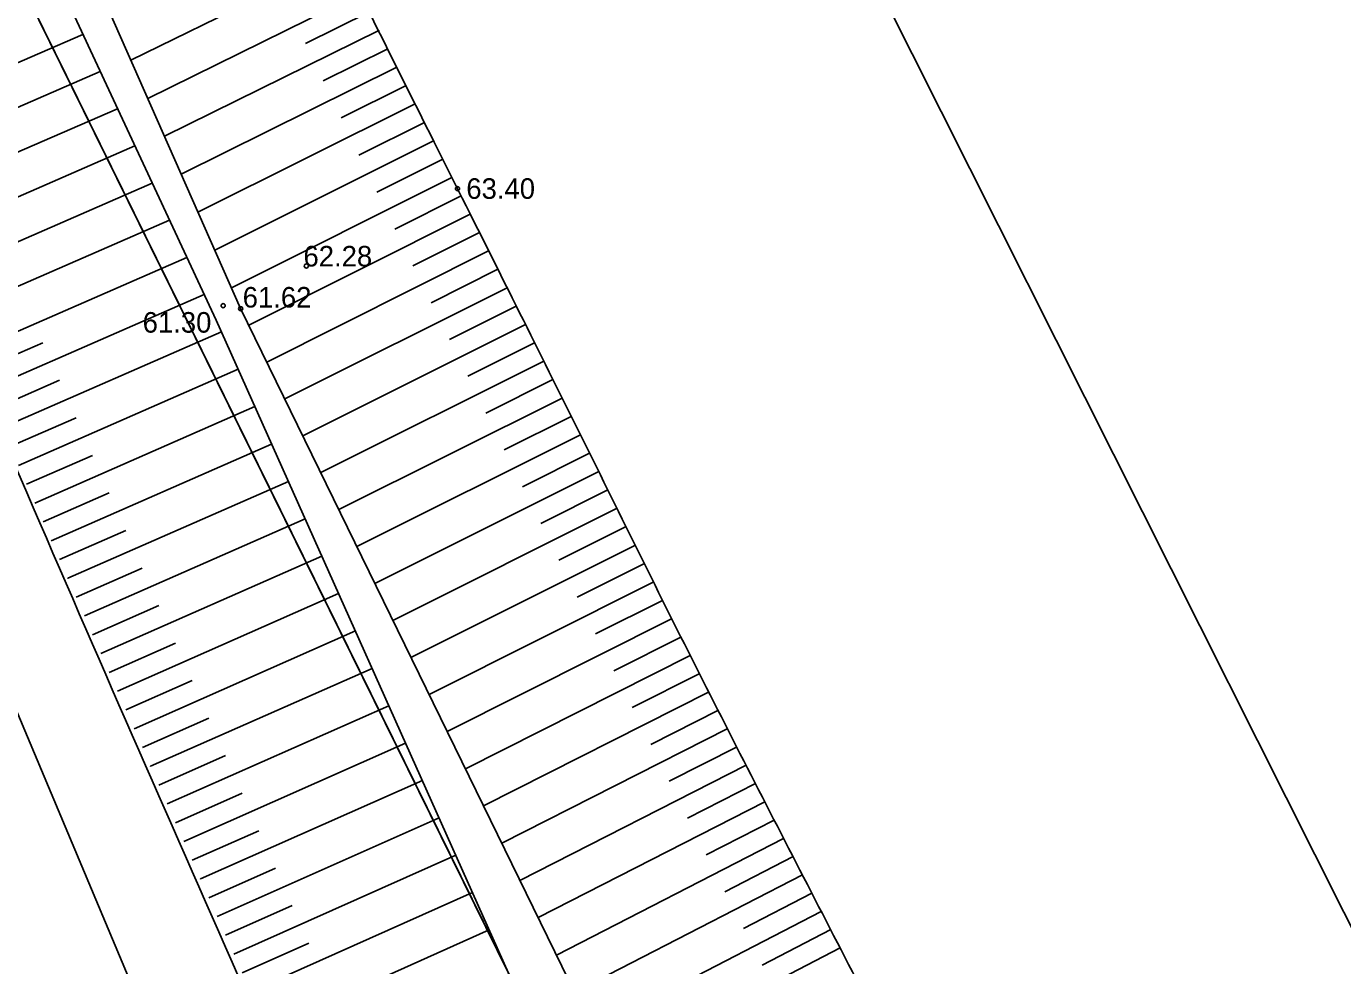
# Model space of a CAD drawing. Extents: x 616607 to 617499, y 408385 to 409695.
# Drawn here: x 617157.39 to 617189.45, y 409191.77 to 409214.63 of the extents above; entities that cross this region are included whole.
import ezdxf

# ---------------------------------------------------------------- set-up
doc = ezdxf.new("R2010")
doc.units = 0
for name, color, linetype in [('HIDG_GRAV_####_####_#', 7, 'Continuous'), ('RAMI_UZMR_####_####_#', 7, 'Continuous'), ('RELJ_AATZ_####_TKST_#', 7, 'Continuous'), ('RELJ_ELEM_####_####_#', 7, 'Continuous'), ('RELJ_NOGA_####_####_#', 7, 'Continuous'), ('ROBZ_IERR_####_####_#', 7, 'Continuous'), ('ROBZ_UZMR_####_####_#', 7, 'Continuous')]:
    doc.layers.add(name, color=color, linetype=linetype)

# ---------------------------------------------------------------- blocks, each defined once
blk = doc.blocks.new('PKT')
at = {"layer": 'RELJ_ELEM_####_####_#'}
blk.add_circle((0, 0), 0.05, dxfattribs=at)

msp = doc.modelspace()

# ---------------------------------------------------------------- linework, layer by layer
at = {"layer": 'HIDG_GRAV_####_####_#'}
for points in [[(617196.049, 409072.553), (617193.886, 409072.979), (617195.921, 409087.874), (617195.921, 409087.874), (617199.518, 409112.516), (617194.569, 409134.842), (617162.019, 409207.474), (617151.93, 409229.107), (617149.428, 409241.28), (617152.359, 409253.938), (617188.564, 409303.055), (617197.968, 409312.659), (617223.456, 409346.169), (617232.567, 409363.51), (617247.671, 409422.509), (617276.576, 409461.456), (617285.007, 409472.526), (617327.765, 409527.3)], [(617198.671, 409072.074), (617200.929, 409072.435), (617202.532, 409075.622), (617201.237, 409087.874), (617202.422, 409112.516), (617197.415, 409136.544), (617162.613, 409207.758), (617153.021, 409229.447), (617150.525, 409241.262), (617153.298, 409253.658), (617189.431, 409302.264), (617198.754, 409312.12), (617224.478, 409345.652), (617234.105, 409363.027), (617250.009, 409421.44), (617285.914, 409471.848), (617328.6, 409526.531)]]:
    msp.add_lwpolyline(points, dxfattribs=at)
at = {"layer": 'RAMI_UZMR_####_####_#'}
msp.add_lwpolyline([(617101.571, 408748.246), (617213.472, 409074.039), (617215.883, 409140.56), (617165.121, 409241.478), (617252.137, 409353.424), (617269.572, 409425.099), (617332.631, 409510.312), (617439.945, 409622.037), (617425.373, 409635.959), (617242.079, 409440.82), (617216.614, 409355.716), (617136.613, 409246.751), (617191.828, 409115.62), (617145.545, 408952.8)], dxfattribs=at)
at = {"layer": 'RELJ_NOGA_####_####_#'}
for p, q in [((617165.091, 409216.326), (617159.938, 409213.805)), ((617165.532, 409215.428), (617160.349, 409212.875)), ((617165.753, 409214.98), (617164.193, 409214.211)), ((617153.607, 409212.193), (617158.773, 409214.434)), ((617165.974, 409214.531), (617160.757, 409211.955)), ((617165.974, 409214.531), (617165.975, 409214.532)), ((617166.196, 409214.083), (617164.626, 409213.306)), ((617166.196, 409214.083), (617166.196, 409214.083)), ((617154.005, 409211.275), (617159.196, 409213.527)), ((617166.418, 409213.635), (617161.166, 409211.029)), ((617166.418, 409213.635), (617166.419, 409213.636)), ((617166.64, 409213.187), (617165.059, 409212.402)), ((617166.64, 409213.187), (617166.641, 409213.187)), ((617166.863, 409212.74), (617161.574, 409210.107)), ((617166.863, 409212.74), (617166.864, 409212.74)), ((617154.403, 409210.358), (617159.618, 409212.623)), ((617167.086, 409212.292), (617165.494, 409211.497)), ((617167.086, 409212.292), (617167.086, 409212.292)), ((617167.309, 409211.845), (617161.981, 409209.185)), ((617167.309, 409211.845), (617167.31, 409211.845)), ((617154.802, 409209.441), (617160.039, 409211.72)), ((617167.533, 409211.397), (617165.929, 409210.594)), ((617167.533, 409211.397), (617167.533, 409211.398)), ((617155.201, 409208.524), (617160.462, 409210.813)), ((617167.757, 409210.95), (617162.389, 409208.263)), ((617167.757, 409210.95), (617167.758, 409210.951)), ((617167.981, 409210.503), (617166.364, 409209.693)), ((617167.981, 409210.503), (617167.981, 409210.503)), ((617155.6, 409207.607), (617160.883, 409209.91)), ((617168.205, 409210.056), (617162.81, 409207.354)), ((617168.205, 409210.056), (617168.206, 409210.057)), ((617168.429, 409209.609), (617166.809, 409208.798)), ((617168.429, 409209.609), (617168.429, 409209.609)), ((617155.999, 409206.69), (617161.306, 409209.004)), ((617168.652, 409209.162), (617163.247, 409206.459)), ((617168.652, 409209.162), (617168.653, 409209.162)), ((617168.876, 409208.715), (617167.253, 409207.903)), ((617168.876, 409208.715), (617168.876, 409208.715)), ((617169.099, 409208.267), (617163.685, 409205.564)), ((617169.099, 409208.267), (617169.1, 409208.268)), ((617156.399, 409205.774), (617161.726, 409208.101)), ((617169.323, 409207.82), (617167.697, 409207.009)), ((617169.323, 409207.82), (617169.323, 409207.82)), ((617169.546, 409207.373), (617164.124, 409204.666)), ((617169.546, 409207.373), (617169.547, 409207.373)), ((617156.199, 409206.232), (617157.794, 409206.929)), ((617156.8, 409204.857), (617162.145, 409207.193)), ((617169.769, 409206.925), (617168.141, 409206.113)), ((617169.769, 409206.925), (617169.77, 409206.926)), ((617157.201, 409203.941), (617162.553, 409206.283)), ((617169.993, 409206.478), (617164.562, 409203.769)), ((617169.993, 409206.478), (617169.993, 409206.479)), ((617156.6, 409205.316), (617158.201, 409206.015)), ((617170.216, 409206.031), (617168.585, 409205.217)), ((617170.216, 409206.031), (617170.216, 409206.031)), ((617157.602, 409203.025), (617162.96, 409205.373)), ((617170.439, 409205.583), (617165.001, 409202.87)), ((617170.439, 409205.583), (617170.44, 409205.584)), ((617157, 409204.399), (617158.604, 409205.101)), ((617170.662, 409205.136), (617169.03, 409204.321)), ((617170.662, 409205.136), (617170.662, 409205.136)), ((617170.885, 409204.688), (617165.441, 409201.971)), ((617170.885, 409204.688), (617170.886, 409204.689)), ((617158.003, 409202.109), (617163.368, 409204.463)), ((617157.401, 409203.483), (617159.008, 409204.187)), ((617171.109, 409204.241), (617169.474, 409203.425)), ((617171.109, 409204.241), (617171.109, 409204.241)), ((617171.332, 409203.794), (617165.88, 409201.072)), ((617171.332, 409203.794), (617171.333, 409203.794)), ((617157.401, 409203.483), (617157.401, 409203.483)), ((617158.405, 409201.194), (617163.776, 409203.553)), ((617157.802, 409202.567), (617159.411, 409203.273)), ((617171.555, 409203.346), (617169.919, 409202.529)), ((617171.555, 409203.346), (617171.556, 409203.347)), ((617157.602, 409203.025), (617157.601, 409203.025)), ((617171.779, 409202.899), (617166.32, 409200.171)), ((617171.779, 409202.899), (617171.78, 409202.9)), ((617157.802, 409202.567), (617157.802, 409202.567)), ((617158.808, 409200.278), (617164.184, 409202.643)), ((617172.002, 409202.452), (617170.364, 409201.633)), ((617172.002, 409202.452), (617172.003, 409202.452)), ((617158.204, 409201.652), (617159.814, 409202.359)), ((617158.003, 409202.109), (617158.002, 409202.109)), ((617172.226, 409202.005), (617166.761, 409199.269)), ((617172.226, 409202.005), (617172.227, 409202.005)), ((617158.204, 409201.652), (617158.204, 409201.651)), ((617159.211, 409199.363), (617164.592, 409201.734)), ((617172.45, 409201.558), (617170.809, 409200.736)), ((617172.45, 409201.558), (617172.45, 409201.558)), ((617158.405, 409201.194), (617158.404, 409201.193)), ((617158.606, 409200.736), (617160.218, 409201.445)), ((617172.674, 409201.111), (617167.203, 409198.366)), ((617172.674, 409201.111), (617172.675, 409201.111)), ((617158.606, 409200.736), (617158.606, 409200.736)), ((617159.009, 409199.821), (617160.623, 409200.531)), ((617159.614, 409198.448), (617164.999, 409200.824)), ((617172.898, 409200.664), (617171.255, 409199.84)), ((617172.898, 409200.664), (617172.899, 409200.664)), ((617158.808, 409200.278), (617158.807, 409200.278)), ((617173.123, 409200.217), (617167.644, 409197.462)), ((617173.123, 409200.217), (617173.123, 409200.217)), ((617160.018, 409197.533), (617165.407, 409199.915)), ((617159.009, 409199.821), (617159.009, 409199.821)), ((617159.412, 409198.906), (617161.027, 409199.617)), ((617173.347, 409199.77), (617171.702, 409198.943)), ((617173.347, 409199.77), (617173.347, 409199.77)), ((617159.211, 409199.363), (617159.21, 409199.363)), ((617173.572, 409199.323), (617168.086, 409196.559)), ((617173.572, 409199.323), (617173.573, 409199.324)), ((617160.422, 409196.619), (617165.816, 409199.002)), ((617159.412, 409198.906), (617159.412, 409198.905)), ((617159.816, 409197.991), (617161.432, 409198.704)), ((617173.797, 409198.877), (617172.149, 409198.047)), ((617173.797, 409198.877), (617173.797, 409198.877)), ((617159.614, 409198.448), (617159.613, 409198.448)), ((617174.022, 409198.431), (617168.527, 409195.655)), ((617174.022, 409198.431), (617174.023, 409198.431)), ((617159.816, 409197.991), (617159.816, 409197.99)), ((617160.827, 409195.704), (617166.223, 409198.093)), ((617174.248, 409197.984), (617172.598, 409197.149)), ((617174.248, 409197.984), (617174.248, 409197.984)), ((617160.22, 409197.076), (617161.837, 409197.791)), ((617160.018, 409197.533), (617160.017, 409197.533)), ((617174.473, 409197.538), (617168.969, 409194.752)), ((617174.473, 409197.538), (617174.474, 409197.539)), ((617160.22, 409197.076), (617160.22, 409197.076)), ((617161.232, 409194.79), (617166.63, 409197.184)), ((617174.7, 409197.092), (617173.047, 409196.254)), ((617174.7, 409197.092), (617174.7, 409197.092)), ((617160.624, 409196.161), (617162.243, 409196.878)), ((617160.422, 409196.619), (617160.421, 409196.618)), ((617174.926, 409196.647), (617169.413, 409193.843)), ((617174.926, 409196.647), (617174.927, 409196.647)), ((617160.624, 409196.161), (617160.624, 409196.161)), ((617161.638, 409193.876), (617167.038, 409196.275)), ((617175.153, 409196.201), (617173.497, 409195.359)), ((617175.153, 409196.201), (617175.153, 409196.201)), ((617161.029, 409195.247), (617162.648, 409195.965)), ((617175.38, 409195.755), (617169.855, 409192.937)), ((617175.38, 409195.755), (617175.381, 409195.756)), ((617160.827, 409195.704), (617160.826, 409195.704)), ((617161.029, 409195.247), (617161.029, 409195.247)), ((617162.044, 409192.962), (617167.445, 409195.367)), ((617175.607, 409195.31), (617173.948, 409194.462)), ((617175.607, 409195.31), (617175.608, 409195.31)), ((617161.232, 409194.79), (617161.231, 409194.789)), ((617161.435, 409194.333), (617163.055, 409195.051)), ((617175.835, 409194.865), (617170.301, 409192.026)), ((617175.835, 409194.865), (617175.836, 409194.865)), ((617162.45, 409192.049), (617167.854, 409194.454)), ((617161.435, 409194.333), (617161.434, 409194.333)), ((617161.841, 409193.419), (617163.461, 409194.139)), ((617176.063, 409194.42), (617174.4, 409193.567)), ((617176.063, 409194.42), (617176.064, 409194.42)), ((617161.638, 409193.876), (617161.637, 409193.875)), ((617176.292, 409193.976), (617170.744, 409191.119)), ((617176.292, 409193.976), (617176.293, 409193.976)), ((617162.858, 409191.135), (617168.261, 409193.546)), ((617176.521, 409193.531), (617174.855, 409192.67)), ((617176.521, 409193.531), (617176.521, 409193.531)), ((617161.841, 409193.419), (617161.84, 409193.419)), ((617162.247, 409192.505), (617163.868, 409193.227)), ((617162.044, 409192.962), (617162.043, 409192.962)), ((617176.75, 409193.087), (617171.187, 409190.213)), ((617176.75, 409193.087), (617176.751, 409193.087)), ((617162.247, 409192.505), (617162.247, 409192.505)), ((617163.265, 409190.222), (617168.668, 409192.638)), ((617176.98, 409192.643), (617175.308, 409191.779)), ((617176.98, 409192.643), (617176.98, 409192.643)), ((617162.654, 409191.592), (617164.275, 409192.315)), ((617177.21, 409192.198), (617171.628, 409189.31)), ((617177.21, 409192.198), (617177.21, 409192.199)), ((617162.45, 409192.049), (617162.45, 409192.048))]:
    msp.add_line(p, q, dxfattribs=at)
for points in [[(617336.806, 409523.735), (617334.087, 409521.174), (617331.368, 409518.613), (617328.65, 409516.053), (617321.193, 409509.03), (617314.57, 409501.094), (617308.568, 409492.793), (617305.546, 409488.614), (617302.537, 409484.426), (617299.516, 409480.247), (617296.49, 409476.063), (617293.469, 409471.875), (617290.436, 409467.695), (617287.772, 409464.025), (617284.965, 409460.461), (617282.252, 409456.826), (617279.55, 409453.205), (617276.887, 409449.558), (617274.256, 409445.882), (617271.624, 409442.206), (617269.17, 409438.414), (617266.782, 409434.573), (617265.581, 409432.642), (617264.455, 409430.674), (617263.346, 409428.69), (617262.228, 409426.69), (617261.169, 409424.668), (617260.166, 409422.606), (617258.56, 409419.302), (617257.132, 409415.931), (617255.903, 409412.47), (617254.682, 409409.035), (617253.531, 409405.585), (617252.579, 409402.073), (617251.627, 409398.563), (617250.683, 409395.052), (617249.746, 409391.538), (617248.81, 409388.023), (617247.876, 409384.508), (617246.956, 409380.989), (617246.456, 409379.078), (617246.028, 409377.149), (617245.649, 409375.21), (617245.269, 409373.268), (617244.984, 409371.31), (617244.622, 409369.366), (617244.259, 409367.42), (617243.878, 409365.48), (617243.456, 409363.545), (617243.245, 409362.576), (617242.967, 409361.625), (617242.691, 409360.672), (617242.413, 409359.713), (617242.093, 409358.772), (617241.734, 409357.838), (617241.092, 409356.173), (617240.315, 409354.578), (617239.389, 409353.048), (617238.465, 409351.519), (617237.498, 409350.034), (617236.402, 409348.636), (617235.3, 409347.23), (617234.195, 409345.828), (617233.083, 409344.431), (617231.973, 409343.038), (617230.863, 409341.647), (617229.743, 409340.262), (617227.764, 409337.815), (617225.693, 409335.438), (617223.461, 409333.217), (617221.215, 409330.983), (617218.873, 409328.856), (617216.607, 409326.646), (617214.346, 409324.442), (617212.093, 409322.231), (617209.875, 409319.98), (617208.771, 409318.86), (617207.791, 409317.635), (617206.772, 409316.432), (617205.753, 409315.229), (617204.825, 409314.017), (617203.96, 409312.646), (617203.768, 409312.342), (617203.633, 409312.004), (617203.62, 409311.655), (617203.607, 409311.284), (617203.603, 409310.913), (617203.599, 409310.542), (617203.595, 409310.167), (617203.603, 409309.793), (617203.596, 409309.419), (617203.588, 409309.066), (617203.48, 409308.714), (617203.309, 409308.4), (617202.615, 409307.13), (617201.9, 409305.914), (617201.16, 409304.689), (617200.419, 409303.462), (617199.689, 409302.232), (617198.921, 409301.021), (617197.385, 409298.6), (617195.744, 409296.251), (617194.012, 409293.966), (617188.331, 409286.47), (617182.548, 409279.072), (617176.617, 409271.78), (617175.091, 409269.904), (617173.565, 409268.03), (617172.006, 409266.181), (617170.46, 409264.348), (617168.875, 409262.548), (617167.326, 409260.717), (617165.749, 409258.854), (617164.19, 409256.978), (617162.652, 409255.082), (617161.86, 409254.106), (617161.109, 409253.1), (617160.341, 409252.105), (617159.552, 409251.081), (617158.796, 409250.055), (617158.061, 409248.97), (617157.091, 409247.54), (617156.549, 409245.874), (617156.301, 409244.175), (617156.178, 409243.327), (617156.153, 409242.478), (617156.175, 409241.631), (617156.198, 409240.798), (617156.24, 409239.966), (617156.347, 409239.134), (617156.709, 409236.311), (617157.141, 409233.481), (617158.294, 409230.866), (617161.329, 409223.986), (617164.552, 409217.339), (617167.894, 409210.677), (617170.758, 409204.966), (617173.578, 409199.236), (617176.506, 409193.56), (617179.423, 409187.907), (617182.384, 409182.277), (617185.301, 409176.624), (617188.243, 409170.922), (617191.171, 409165.213), (617194.071, 409159.489), (617195.541, 409156.585), (617196.952, 409153.652), (617198.382, 409150.727), (617199.832, 409147.761), (617201.227, 409144.774), (617202.61, 409141.772), (617203.681, 409139.449), (617204.533, 409137.047), (617205.282, 409134.589), (617206.022, 409132.164), (617206.554, 409129.71), (617206.943, 409127.212), (617207.329, 409124.726), (617207.611, 409122.242), (617207.809, 409119.738), (617208.005, 409117.248), (617208.126, 409114.753), (617208.097, 409112.263), (617208.074, 409110.266), (617207.983, 409108.256), (617207.635, 409106.282), (617207.283, 409104.281), (617206.913, 409102.294), (617206.558, 409100.3), (617206.203, 409098.306), (617205.85, 409096.331), (617205.506, 409094.315), (617205.165, 409092.324), (617205.06, 409090.322), (617205.116, 409088.325), (617205.171, 409086.355), (617205.316, 409084.384), (617205.484, 409082.414), (617205.653, 409080.435), (617205.914, 409078.469), (617206.09, 409076.495), (617206.126, 409076.085), (617206.005, 409075.66), (617206.103, 409075.26)], [(617191.5, 409068.875), (617191.187, 409071.639), (617190.873, 409074.403), (617190.56, 409077.167), (617188.889, 409091.892), (617197.619, 409106.66), (617195.165, 409121.386), (617194.844, 409123.312), (617194.157, 409125.135), (617193.325, 409126.9), (617187.756, 409138.717), (617181.857, 409150.154), (617176.29, 409161.887), (617165.241, 409185.172), (617154.985, 409208.835), (617144.902, 409232.447), (617143.246, 409236.327), (617146.946, 409242.229), (617143.832, 409245.09), (617142.81, 409246.028), (617141.789, 409246.966), (617140.768, 409247.904)]]:
    msp.add_open_spline(points, degree=3, dxfattribs=at)
at = {"layer": 'ROBZ_IERR_####_####_#'}
msp.add_lwpolyline([(617119.605, 409263.967), (617148.652, 409247.272), (617150.138, 409230.13), (617196.507, 409136.07), (617200.886, 409119.423), (617196.025, 409075.262), (617232.282, 409073.757)], dxfattribs=at)
at = {"layer": 'ROBZ_UZMR_####_####_#'}
msp.add_lwpolyline([(617232.583, 409073.745), (617196.025, 409075.262), (617200.886, 409119.423), (617196.507, 409136.07), (617150.138, 409230.13), (617148.652, 409247.272), (617201.229, 409318.934), (617233.453, 409357.938), (617244.928, 409391.934), (617250.98, 409414.497), (617255.789, 409432.426), (617326.39, 409521.291), (617332.188, 409529.592), (617332.358, 409529.835), (617335.391, 409534.333), (617341.051, 409533.641), (617349.913, 409536.856), (617370.73, 409556.7), (617378.749, 409547.935), (617381.343, 409545.1)], dxfattribs=at)

# ---------------------------------------------------------------- block references
at = {"layer": 'RELJ_ELEM_####_####_#'}
for p in [(617167.894, 409210.677), (617164.213, 409208.796), (617162.188, 409207.831), (617162.613, 409207.758)]:
    msp.add_blockref('PKT', p, dxfattribs=at)

# ---------------------------------------------------------------- texts
at = {"layer": 'RELJ_AATZ_####_TKST_#'}
for s, p in [('63.40', (617168.108, 409210.431)), ('62.28', (617164.143, 409208.785)), ('61.62', (617162.663, 409207.785)), ('61.30', (617160.227, 409207.174))]:
    msp.add_text(s, height=0.5, dxfattribs=at).set_placement(p)

doc.saveas('drawing.dxf')
